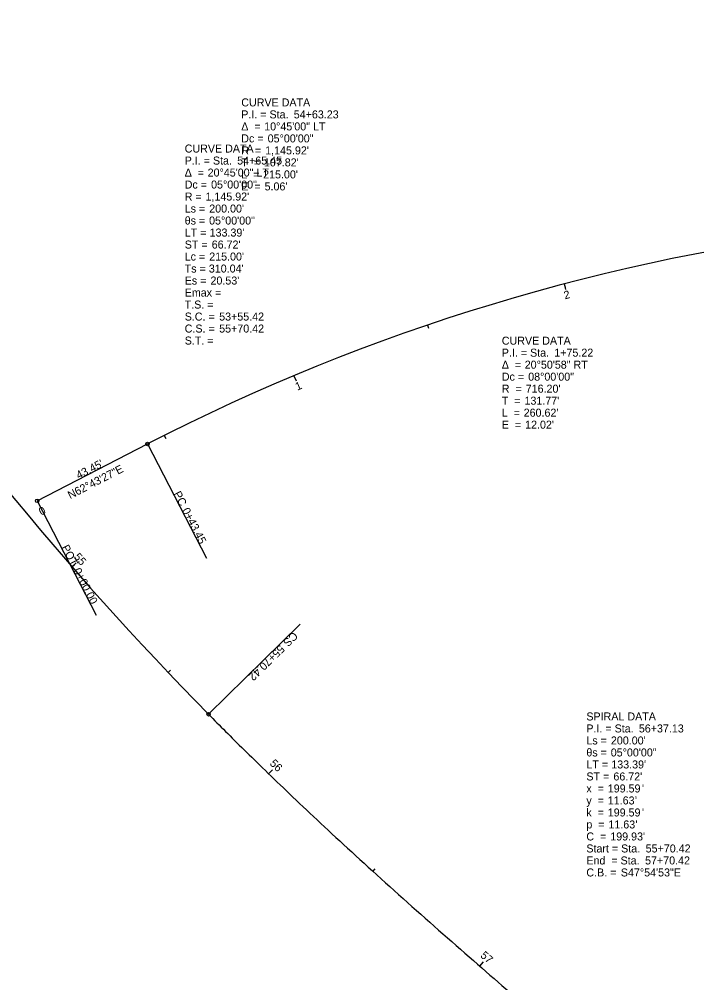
# Model space of a CAD drawing. Extents: x 1492452 to 1496782, y 514026 to 517659.
# Drawn here: x 1494541.8 to 1494779, y 514788.1 to 515125.3 of the extents above; entities that cross this region are included whole.
import ezdxf

# ---------------------------------------------------------------- set-up
doc = ezdxf.new("R2010")
doc.units = 0
for name, color, linetype in [('BR_X_SV_Abut', 7, 'Continuous'), ('Default', 7, 'Continuous'), ('DR_X_Ditch', 7, 'Continuous'), ('DR_X_Elev_Flow', 7, 'Continuous'), ('DT_X_Break_Line', 7, 'Continuous'), ('DT_X_Contour_Minor', 7, 'Continuous'), ('DT_X_Island', 7, 'Continuous'), ('DT_X_TIN_Hull', 7, 'Continuous'), ('DT_X_Triangles', 7, 'Continuous'), ('DT_X_Void', 7, 'Continuous'), ('GE_X_Cells', 7, 'Continuous'), ('PV_X_COP', 7, 'Continuous'), ('PV_X_EOP', 7, 'Continuous'), ('PV_X_Shoulder_Aggregate', 7, 'Continuous'), ('RD_X_Cells', 7, 'Continuous'), ('RD_X_GR_Lt', 7, 'Continuous'), ('RD_X_GR_Rt', 7, 'Continuous'), ('RD_X_Wall', 7, 'Continuous'), ('SN_X_Public', 7, 'Continuous'), ('SV_X_Random_Point', 7, 'Continuous'), ('SV_X_Top_of_Bank', 7, 'Continuous'), ('UT_X_Electric_Cells', 7, 'Continuous'), ('UT_X_Misc_Cells', 7, 'Continuous'), ('UT_X_Water', 7, 'Continuous'), ('UT_X_Water_Cells', 7, 'Continuous'), ('VG_X_Cells', 7, 'Continuous'), ('XS_X_Ground_Line', 7, 'Continuous')]:
    doc.layers.add(name, color=color, linetype=linetype)

msp = doc.modelspace()

# ---------------------------------------------------------------- linework, layer by layer
at = {"layer": 'Default'}
msp.add_line((1494548.11, 514956.7), (1494586.73, 514976.61), dxfattribs=at)
for centre, radius, start, end in [((1486425.91, 524780.42), 12277.67, 302.444021, 313.600151), ((1494914.94, 514340.04), 716.2, 96.42645, 117.27596)]:
    msp.add_arc(centre, radius, start, end, dxfattribs=at)
at = {"layer": 'DT_X_Contour_Minor'}
msp.add_line((1494560.25, 514933.64), (1494561.16, 514934.43), dxfattribs=at)
at = {"layer": 'DT_X_TIN_Hull'}
for p, q in [((1494732.57, 515032.63), (1494733.08, 515030.7)), ((1494684.7, 515018.23), (1494685.09, 515017.09)), ((1494637.96, 515000.51), (1494638.73, 514998.67)), ((1494592.56, 514979.58), (1494593.1, 514978.51)), ((1494548.11, 514956.7), (1494549.02, 514954.92))]:
    msp.add_line(p, q, dxfattribs=at)
at = {"layer": 'DT_X_Void'}
for p, q in [((1494586.73, 514976.61), (1494607.35, 514936.61)), ((1494548.11, 514956.7), (1494568.73, 514916.7))]:
    msp.add_line(p, q, dxfattribs=at)
for centre in [(1494586.73, 514976.61), (1494548.11, 514956.7)]:
    msp.add_circle(centre, 0.6, dxfattribs=at)
at = {"layer": 'GE_X_Cells'}
msp.add_line((1494548.11, 514956.7), (1494586.73, 514976.61), dxfattribs=at)
for centre, radius, start, end in [((1486425.91, 524780.42), 12277.67, 302.444021, 313.600151), ((1494914.94, 514340.04), 716.2, 96.42645, 117.27596)]:
    msp.add_arc(centre, radius, start, end, dxfattribs=at)
at = {"layer": 'PV_X_EOP'}
msp.add_line((1494608.11, 514882), (1494640.16, 514913.59), dxfattribs=at)
msp.add_circle((1494608.11, 514882), 0.6, dxfattribs=at)
at = {"layer": 'PV_X_Shoulder_Aggregate'}
for p, q in [((1494560.25, 514933.64), (1494561.76, 514934.96)), ((1494593.91, 514896.67), (1494594.78, 514897.5)), ((1494629.13, 514861.19), (1494630.52, 514862.62)), ((1494665.64, 514827.03), (1494666.45, 514827.92)), ((1494703.04, 514793.85), (1494704.36, 514795.36))]:
    msp.add_line(p, q, dxfattribs=at)
at = {"layer": 'RD_X_Cells'}
for p, q in [((1494586.73, 514976.61), (1494607.35, 514936.61)), ((1494548.11, 514956.7), (1494568.73, 514916.7))]:
    msp.add_line(p, q, dxfattribs=at)
for centre in [(1494586.73, 514976.61), (1494548.11, 514956.7)]:
    msp.add_circle(centre, 0.6, dxfattribs=at)
at = {"layer": 'RD_X_GR_Rt'}
msp.add_line((1494608.11, 514882), (1494640.16, 514913.59), dxfattribs=at)
msp.add_circle((1494608.11, 514882), 0.6, dxfattribs=at)
at = {"layer": 'RD_X_Wall'}
for p, q in [((1494560.25, 514933.64), (1494561.76, 514934.96)), ((1494629.13, 514861.19), (1494629.97, 514862.05)), ((1494703.04, 514793.85), (1494703.83, 514794.75))]:
    msp.add_line(p, q, dxfattribs=at)
at = {"layer": 'SV_X_Top_of_Bank'}
msp.add_arc((1495424.3, 515686.35), 1145.92, 213.83122, 224.58118, dxfattribs=at)
msp.add_arc((1495424.3, 515686.35), 1145.92, 213.83122, 224.58118, dxfattribs=at)
msp.add_open_spline([(1494608.11, 514882), (1494612.01, 514878.04), (1494619.86, 514870.19), (1494635.79, 514854.68), (1494656.04, 514835.67), (1494680.78, 514813.33), (1494705.84, 514791.35), (1494726.9, 514773.23), (1494743.8, 514758.81), (1494752.26, 514751.6), (1494756.49, 514748)], degree=3, dxfattribs=at)
msp.add_open_spline([(1494608.11, 514882), (1494612.01, 514878.04), (1494619.86, 514870.19), (1494635.79, 514854.68), (1494656.04, 514835.67), (1494680.78, 514813.33), (1494705.84, 514791.35), (1494726.9, 514773.23), (1494743.8, 514758.81), (1494752.26, 514751.6), (1494756.49, 514748)], degree=3, dxfattribs=at)
at = {"layer": 'UT_X_Misc_Cells'}
for p, q in [((1494586.73, 514976.61), (1494607.35, 514936.61)), ((1494548.11, 514956.7), (1494568.73, 514916.7))]:
    msp.add_line(p, q, dxfattribs=at)
for centre in [(1494586.73, 514976.61), (1494548.11, 514956.7)]:
    msp.add_circle(centre, 0.6, dxfattribs=at)
at = {"layer": 'UT_X_Water_Cells'}
for p, q in [((1494732.57, 515032.63), (1494732.88, 515031.47)), ((1494637.96, 515000.51), (1494638.42, 514999.41)), ((1494548.11, 514956.7), (1494549.02, 514954.92))]:
    msp.add_line(p, q, dxfattribs=at)
at = {"layer": 'VG_X_Cells'}
msp.add_line((1494548.11, 514956.7), (1494549.02, 514954.92), dxfattribs=at)
at = {"layer": 'XS_X_Ground_Line'}
msp.add_line((1494608.11, 514882), (1494640.16, 514913.59), dxfattribs=at)
msp.add_circle((1494608.11, 514882), 0.6, dxfattribs=at)

# ---------------------------------------------------------------- texts
at = {"layer": 'BR_X_SV_Abut'}
for s, p in [('CURVE DATA', (1494619.55, 515094.76)), ('P.I. = Sta. ', (1494619.55, 515090.56)), ('54+63.23', (1494637.92, 515090.56)), ('Δ  = ', (1494619.55, 515086.36)), ('10°45\'00" LT', (1494627.57, 515086.36)), ('Dc = ', (1494619.55, 515082.16)), ('05°00\'00"', (1494628.79, 515082.16)), ('CURVE DATA', (1494599.74, 515078.61)), ('R  = ', (1494619.55, 515077.96)), ("1,145.92'", (1494627.92, 515077.96)), ('P.I. = Sta. ', (1494599.74, 515074.41)), ('54+65.45', (1494618.11, 515074.41)), ('T  = ', (1494619.55, 515073.76)), ("107.82'", (1494627.48, 515073.76)), ('Δ  = ', (1494599.74, 515070.21)), ('20°45\'00" LT', (1494607.77, 515070.21)), ('L  = ', (1494619.55, 515069.56)), ("215.00'", (1494627.2, 515069.56)), ('Dc = ', (1494599.74, 515066.01)), ('05°00\'00"', (1494608.98, 515066.01)), ('E  = ', (1494619.55, 515065.36)), ("5.06'", (1494627.7, 515065.36)), ('R = ', (1494599.74, 515061.81)), ("1,145.92'", (1494607.02, 515061.81)), ('Ls = ', (1494599.74, 515057.61)), ("200.00'", (1494608.33, 515057.61)), ('θs = ', (1494599.74, 515053.41)), ('05°00\'00"', (1494608.28, 515053.41)), ('LT = ', (1494599.74, 515049.21)), ("133.39'", (1494608.47, 515049.21)), ('ST = ', (1494599.74, 515045.01)), ("66.72'", (1494609.2, 515045.01)), ('Lc = ', (1494599.74, 515040.81)), ("215.00'", (1494608.33, 515040.81)), ('Ts = ', (1494599.74, 515036.61)), ("310.04'", (1494608.19, 515036.61)), ('Es = ', (1494599.74, 515032.41)), ("20.53'", (1494608.77, 515032.41)), ('Emax = ', (1494599.74, 515028.21)), ('T.S. = ', (1494599.74, 515024.01)), ('S.C. = ', (1494599.74, 515019.81)), ('53+55.42', (1494611.81, 515019.81)), ('C.S. = ', (1494599.74, 515015.61)), ('55+70.42', (1494611.81, 515015.61)), ('S.T. = ', (1494599.74, 515011.41)), ('SPIRAL DATA', (1494740.35, 514879.85)), ('P.I. = Sta. ', (1494740.35, 514875.65)), ('56+37.13', (1494758.72, 514875.65)), ('Ls = ', (1494740.35, 514871.45)), ("200.00'", (1494748.94, 514871.45)), ('θs = ', (1494740.35, 514867.25)), ('05°00\'00"', (1494748.89, 514867.25)), ('LT = ', (1494740.35, 514863.05)), ("133.39'", (1494749.08, 514863.05)), ('ST = ', (1494740.35, 514858.85)), ("66.72'", (1494749.81, 514858.85)), ('199.59', (1494747.85, 514854.65)), ("'", (1494759.81, 514854.65)), ('x  = ', (1494740.35, 514854.65)), ('y  = ', (1494740.35, 514850.45)), ('11.63', (1494747.85, 514850.45)), ("'", (1494757.35, 514850.45)), ('k  = ', (1494740.35, 514846.25)), ('199.59', (1494747.85, 514846.25)), ("'", (1494759.81, 514846.25)), ('p  = ', (1494740.35, 514842.05)), ('11.63', (1494748.07, 514842.05)), ("'", (1494757.56, 514842.05)), ('C  = ', (1494740.35, 514837.85)), ("199.93'", (1494748.72, 514837.85)), ('Start = Sta. ', (1494740.35, 514833.65)), ('55+70.42', (1494761.11, 514833.65)), ('End  = Sta. ', (1494740.35, 514829.45)), ('57+70.42', (1494760.9, 514829.45)), ('C.B. = ', (1494740.35, 514825.25)), ('S47°54\'53"E', (1494752.42, 514825.25))]:
    msp.add_text(s, height=2.8, dxfattribs=at).set_placement(p)
at = {"layer": 'DR_X_Ditch'}
msp.add_text("43.45'", height=2.8, rotation=27.276, dxfattribs=at).set_placement((1494562.6, 514964.22))
at = {"layer": 'DR_X_Elev_Flow'}
for s, p in [('CURVE DATA', (1494710.75, 515011.37)), ('P.I. = Sta. ', (1494710.75, 515007.17)), ('1+75.22', (1494729.12, 515007.17)), ('Δ  = ', (1494710.75, 515002.97)), ('20°50\'58" RT', (1494718.77, 515002.97)), ('Dc = ', (1494710.75, 514998.77)), ('08°00\'00"', (1494719.99, 514998.77)), ('R  = ', (1494710.75, 514994.57)), ("716.20'", (1494719.12, 514994.57)), ('T  = ', (1494710.75, 514990.37)), ("131.77'", (1494718.69, 514990.37)), ('L  = ', (1494710.75, 514986.17)), ("260.62'", (1494718.4, 514986.17)), ('E  = ', (1494710.75, 514981.97)), ("12.02'", (1494718.91, 514981.97))]:
    msp.add_text(s, height=2.8, dxfattribs=at).set_placement(p)
at = {"layer": 'DT_X_Break_Line'}
msp.add_text('N62°43\'27"E', height=2.8, rotation=27.276, dxfattribs=at).set_placement((1494559.68, 514957.26))
at = {"layer": 'DT_X_Island'}
for s, p in [('CURVE DATA', (1494710.75, 515011.37)), ('P.I. = Sta. ', (1494710.75, 515007.17)), ('1+75.22', (1494729.12, 515007.17)), ('Δ  = ', (1494710.75, 515002.97)), ('20°50\'58" RT', (1494718.77, 515002.97)), ('Dc = ', (1494710.75, 514998.77)), ('08°00\'00"', (1494719.99, 514998.77)), ('R  = ', (1494710.75, 514994.57)), ("716.20'", (1494719.12, 514994.57)), ('T  = ', (1494710.75, 514990.37)), ("131.77'", (1494718.69, 514990.37)), ('L  = ', (1494710.75, 514986.17)), ("260.62'", (1494718.4, 514986.17)), ('E  = ', (1494710.75, 514981.97)), ("12.02'", (1494718.91, 514981.97))]:
    msp.add_text(s, height=2.8, dxfattribs=at).set_placement(p)
at = {"layer": 'DT_X_TIN_Hull'}
for s, rotation, p in [('2', 14.752, (1494732.86, 515027.23)), ('1', 22.752, (1494639.14, 514995.26)), ('0', 27.276, (1494549.55, 514951.48))]:
    msp.add_text(s, height=2.8, rotation=rotation, dxfattribs=at).set_placement(p)
at = {"layer": 'DT_X_Triangles'}
for s, p in [('CURVE DATA', (1494619.55, 515094.76)), ('P.I. = Sta. ', (1494619.55, 515090.56)), ('54+63.23', (1494637.92, 515090.56)), ('Δ  = ', (1494619.55, 515086.36)), ('10°45\'00" LT', (1494627.57, 515086.36)), ('Dc = ', (1494619.55, 515082.16)), ('05°00\'00"', (1494628.79, 515082.16)), ('CURVE DATA', (1494599.74, 515078.61)), ('R  = ', (1494619.55, 515077.96)), ("1,145.92'", (1494627.92, 515077.96)), ('P.I. = Sta. ', (1494599.74, 515074.41)), ('54+65.45', (1494618.11, 515074.41)), ('T  = ', (1494619.55, 515073.76)), ("107.82'", (1494627.48, 515073.76)), ('Δ  = ', (1494599.74, 515070.21)), ('20°45\'00" LT', (1494607.77, 515070.21)), ('L  = ', (1494619.55, 515069.56)), ("215.00'", (1494627.2, 515069.56)), ('Dc = ', (1494599.74, 515066.01)), ('05°00\'00"', (1494608.98, 515066.01)), ('E  = ', (1494619.55, 515065.36)), ("5.06'", (1494627.7, 515065.36)), ('R = ', (1494599.74, 515061.81)), ("1,145.92'", (1494607.02, 515061.81)), ('Ls = ', (1494599.74, 515057.61)), ("200.00'", (1494608.33, 515057.61)), ('θs = ', (1494599.74, 515053.41)), ('05°00\'00"', (1494608.28, 515053.41)), ('LT = ', (1494599.74, 515049.21)), ("133.39'", (1494608.47, 515049.21)), ('ST = ', (1494599.74, 515045.01)), ("66.72'", (1494609.2, 515045.01)), ('Lc = ', (1494599.74, 515040.81)), ("215.00'", (1494608.33, 515040.81)), ('Ts = ', (1494599.74, 515036.61)), ("310.04'", (1494608.19, 515036.61)), ('Es = ', (1494599.74, 515032.41)), ("20.53'", (1494608.77, 515032.41)), ('Emax = ', (1494599.74, 515028.21)), ('T.S. = ', (1494599.74, 515024.01)), ('S.C. = ', (1494599.74, 515019.81)), ('53+55.42', (1494611.81, 515019.81)), ('C.S. = ', (1494599.74, 515015.61)), ('55+70.42', (1494611.81, 515015.61)), ('S.T. = ', (1494599.74, 515011.41)), ('SPIRAL DATA', (1494740.35, 514879.85)), ('P.I. = Sta. ', (1494740.35, 514875.65)), ('56+37.13', (1494758.72, 514875.65)), ('Ls = ', (1494740.35, 514871.45)), ("200.00'", (1494748.94, 514871.45)), ('θs = ', (1494740.35, 514867.25)), ('05°00\'00"', (1494748.89, 514867.25)), ('LT = ', (1494740.35, 514863.05)), ("133.39'", (1494749.08, 514863.05)), ('ST = ', (1494740.35, 514858.85)), ("66.72'", (1494749.81, 514858.85)), ('199.59', (1494747.85, 514854.65)), ("'", (1494759.81, 514854.65)), ('x  = ', (1494740.35, 514854.65)), ('y  = ', (1494740.35, 514850.45)), ('11.63', (1494747.85, 514850.45)), ("'", (1494757.35, 514850.45)), ('k  = ', (1494740.35, 514846.25)), ('199.59', (1494747.85, 514846.25)), ("'", (1494759.81, 514846.25)), ('p  = ', (1494740.35, 514842.05)), ('11.63', (1494748.07, 514842.05)), ("'", (1494757.56, 514842.05)), ('C  = ', (1494740.35, 514837.85)), ("199.93'", (1494748.72, 514837.85)), ('Start = Sta. ', (1494740.35, 514833.65)), ('55+70.42', (1494761.11, 514833.65)), ('End  = Sta. ', (1494740.35, 514829.45)), ('57+70.42', (1494760.9, 514829.45)), ('C.B. = ', (1494740.35, 514825.25)), ('S47°54\'53"E', (1494752.42, 514825.25))]:
    msp.add_text(s, height=2.8, dxfattribs=at).set_placement(p)
at = {"layer": 'DT_X_Void'}
for s, p in [('PC', (1494595.74, 514959.22)), ('0+43.45', (1494598.73, 514953.42)), ('POT', (1494556.53, 514940.46)), ('0+00.00', (1494560.72, 514932.34))]:
    msp.add_text(s, height=2.8, rotation=297.276, dxfattribs=at).set_placement(p)
at = {"layer": 'PV_X_COP'}
for s, p in [('CURVE DATA', (1494619.55, 515094.76)), ('P.I. = Sta. ', (1494619.55, 515090.56)), ('54+63.23', (1494637.92, 515090.56)), ('Δ  = ', (1494619.55, 515086.36)), ('10°45\'00" LT', (1494627.57, 515086.36)), ('Dc = ', (1494619.55, 515082.16)), ('05°00\'00"', (1494628.79, 515082.16)), ('CURVE DATA', (1494599.74, 515078.61)), ('R  = ', (1494619.55, 515077.96)), ("1,145.92'", (1494627.92, 515077.96)), ('P.I. = Sta. ', (1494599.74, 515074.41)), ('54+65.45', (1494618.11, 515074.41)), ('T  = ', (1494619.55, 515073.76)), ("107.82'", (1494627.48, 515073.76)), ('Δ  = ', (1494599.74, 515070.21)), ('20°45\'00" LT', (1494607.77, 515070.21)), ('L  = ', (1494619.55, 515069.56)), ("215.00'", (1494627.2, 515069.56)), ('Dc = ', (1494599.74, 515066.01)), ('05°00\'00"', (1494608.98, 515066.01)), ('E  = ', (1494619.55, 515065.36)), ("5.06'", (1494627.7, 515065.36)), ('R = ', (1494599.74, 515061.81)), ("1,145.92'", (1494607.02, 515061.81)), ('Ls = ', (1494599.74, 515057.61)), ("200.00'", (1494608.33, 515057.61)), ('θs = ', (1494599.74, 515053.41)), ('05°00\'00"', (1494608.28, 515053.41)), ('LT = ', (1494599.74, 515049.21)), ("133.39'", (1494608.47, 515049.21)), ('ST = ', (1494599.74, 515045.01)), ("66.72'", (1494609.2, 515045.01)), ('Lc = ', (1494599.74, 515040.81)), ("215.00'", (1494608.33, 515040.81)), ('Ts = ', (1494599.74, 515036.61)), ("310.04'", (1494608.19, 515036.61)), ('Es = ', (1494599.74, 515032.41)), ("20.53'", (1494608.77, 515032.41)), ('Emax = ', (1494599.74, 515028.21)), ('T.S. = ', (1494599.74, 515024.01)), ('S.C. = ', (1494599.74, 515019.81)), ('53+55.42', (1494611.81, 515019.81)), ('C.S. = ', (1494599.74, 515015.61)), ('55+70.42', (1494611.81, 515015.61)), ('S.T. = ', (1494599.74, 515011.41)), ('SPIRAL DATA', (1494740.35, 514879.85)), ('P.I. = Sta. ', (1494740.35, 514875.65)), ('56+37.13', (1494758.72, 514875.65)), ('Ls = ', (1494740.35, 514871.45)), ("200.00'", (1494748.94, 514871.45)), ('θs = ', (1494740.35, 514867.25)), ('05°00\'00"', (1494748.89, 514867.25)), ('LT = ', (1494740.35, 514863.05)), ("133.39'", (1494749.08, 514863.05)), ('ST = ', (1494740.35, 514858.85)), ("66.72'", (1494749.81, 514858.85)), ('199.59', (1494747.85, 514854.65)), ("'", (1494759.81, 514854.65)), ('x  = ', (1494740.35, 514854.65)), ('y  = ', (1494740.35, 514850.45)), ('11.63', (1494747.85, 514850.45)), ("'", (1494757.35, 514850.45)), ('k  = ', (1494740.35, 514846.25)), ('199.59', (1494747.85, 514846.25)), ("'", (1494759.81, 514846.25)), ('p  = ', (1494740.35, 514842.05)), ('11.63', (1494748.07, 514842.05)), ("'", (1494757.56, 514842.05)), ('C  = ', (1494740.35, 514837.85)), ("199.93'", (1494748.72, 514837.85)), ('Start = Sta. ', (1494740.35, 514833.65)), ('55+70.42', (1494761.11, 514833.65)), ('End  = Sta. ', (1494740.35, 514829.45)), ('57+70.42', (1494760.9, 514829.45)), ('C.B. = ', (1494740.35, 514825.25)), ('S47°54\'53"E', (1494752.42, 514825.25))]:
    msp.add_text(s, height=2.8, dxfattribs=at).set_placement(p)
at = {"layer": 'PV_X_EOP'}
for s, p in [('CS', (1494637.69, 514911.09)), ('55+70.42', (1494633.04, 514906.51))]:
    msp.add_text(s, height=2.8, rotation=224.5812, dxfattribs=at).set_placement(p)
at = {"layer": 'PV_X_Shoulder_Aggregate'}
for s, rotation, p in [('55', 311.0604, (1494560.73, 514936.98)), ('56', 315.951, (1494629.32, 514864.54)), ('57', 318.9614, (1494703.02, 514797.25))]:
    msp.add_text(s, height=2.8, rotation=rotation, dxfattribs=at).set_placement(p)
at = {"layer": 'RD_X_Cells'}
for s, p in [('PC', (1494595.74, 514959.22)), ('0+43.45', (1494598.73, 514953.42)), ('POT', (1494556.53, 514940.46)), ('0+00.00', (1494560.72, 514932.34))]:
    msp.add_text(s, height=2.8, rotation=297.276, dxfattribs=at).set_placement(p)
at = {"layer": 'RD_X_GR_Lt'}
msp.add_text("43.45'", height=2.8, rotation=27.276, dxfattribs=at).set_placement((1494562.6, 514964.22))
at = {"layer": 'RD_X_GR_Rt'}
for s, p in [('CS', (1494637.69, 514911.09)), ('55+70.42', (1494633.04, 514906.51))]:
    msp.add_text(s, height=2.8, rotation=224.5812, dxfattribs=at).set_placement(p)
at = {"layer": 'RD_X_Wall'}
msp.add_text('55', height=2.8, rotation=311.0604, dxfattribs=at).set_placement((1494560.73, 514936.98))
at = {"layer": 'SN_X_Public'}
for s, p in [('CURVE DATA', (1494710.75, 515011.37)), ('P.I. = Sta. ', (1494710.75, 515007.17)), ('1+75.22', (1494729.12, 515007.17)), ('Δ  = ', (1494710.75, 515002.97)), ('20°50\'58" RT', (1494718.77, 515002.97)), ('Dc = ', (1494710.75, 514998.77)), ('08°00\'00"', (1494719.99, 514998.77)), ('R  = ', (1494710.75, 514994.57)), ("716.20'", (1494719.12, 514994.57)), ('T  = ', (1494710.75, 514990.37)), ("131.77'", (1494718.69, 514990.37)), ('L  = ', (1494710.75, 514986.17)), ("260.62'", (1494718.4, 514986.17)), ('E  = ', (1494710.75, 514981.97)), ("12.02'", (1494718.91, 514981.97))]:
    msp.add_text(s, height=2.8, dxfattribs=at).set_placement(p)
at = {"layer": 'SV_X_Random_Point'}
msp.add_text('N62°43\'27"E', height=2.8, rotation=27.276, dxfattribs=at).set_placement((1494559.68, 514957.26))
at = {"layer": 'UT_X_Electric_Cells'}
msp.add_text('N62°43\'27"E', height=2.8, rotation=27.276, dxfattribs=at).set_placement((1494559.68, 514957.26))
at = {"layer": 'UT_X_Misc_Cells'}
for s, p in [('PC', (1494595.74, 514959.22)), ('0+43.45', (1494598.73, 514953.42)), ('POT', (1494556.53, 514940.46)), ('0+00.00', (1494560.72, 514932.34))]:
    msp.add_text(s, height=2.8, rotation=297.276, dxfattribs=at).set_placement(p)
at = {"layer": 'UT_X_Water'}
msp.add_text("43.45'", height=2.8, rotation=27.276, dxfattribs=at).set_placement((1494562.6, 514964.22))
at = {"layer": 'UT_X_Water_Cells'}
msp.add_text('0', height=2.8, rotation=27.276, dxfattribs=at).set_placement((1494549.55, 514951.48))
at = {"layer": 'VG_X_Cells'}
msp.add_text('0', height=2.8, rotation=27.276, dxfattribs=at).set_placement((1494549.55, 514951.48))
at = {"layer": 'XS_X_Ground_Line'}
for s, p in [('CS', (1494637.69, 514911.09)), ('55+70.42', (1494633.04, 514906.51))]:
    msp.add_text(s, height=2.8, rotation=224.5812, dxfattribs=at).set_placement(p)

doc.saveas('drawing.dxf')
